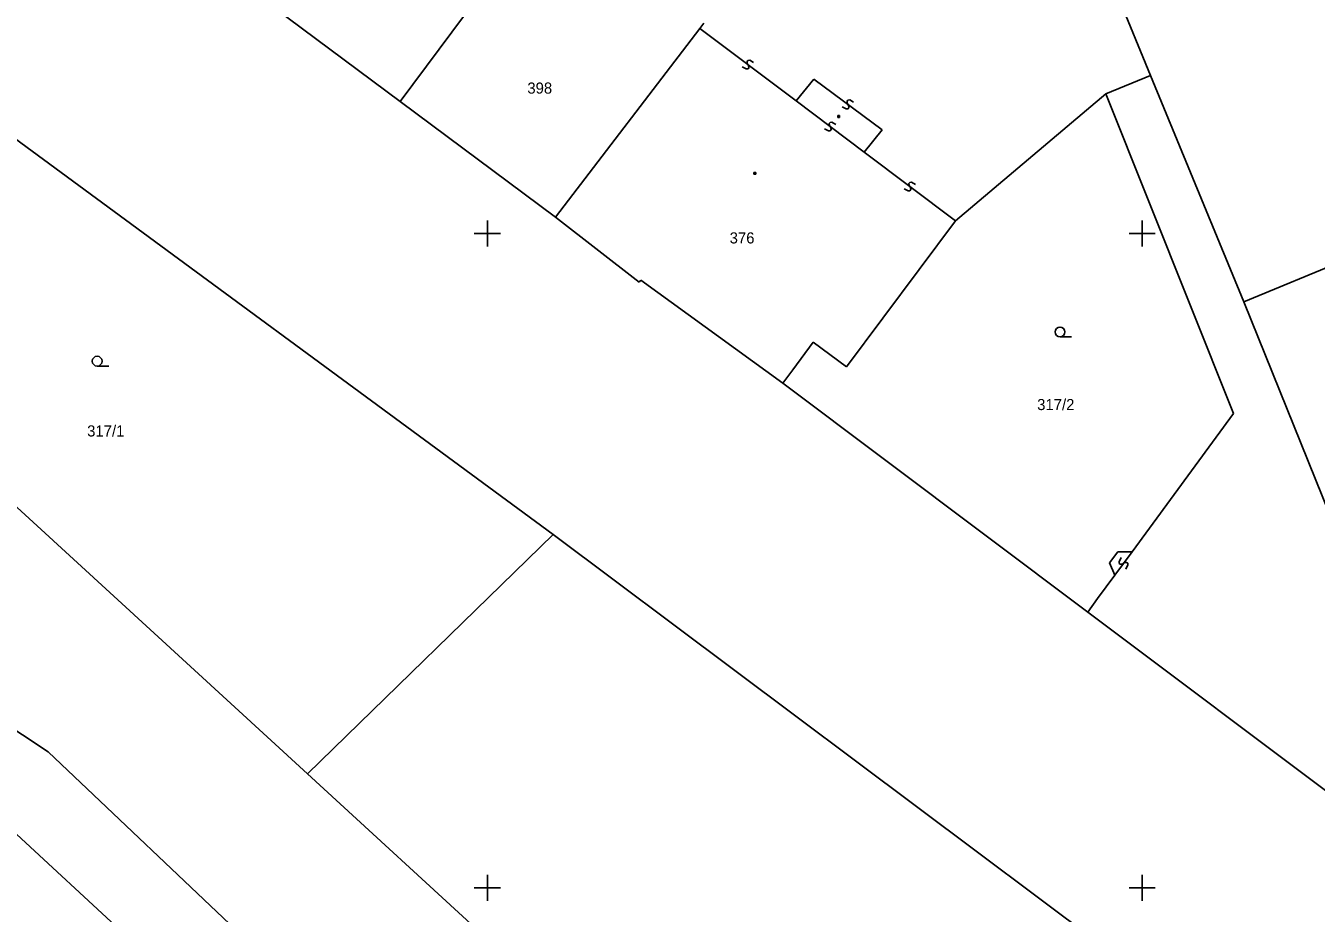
# Model space of a CAD drawing. Extents: x -492379 to -491966, y -1126153 to -1125860.
# Drawn here: x -492201.2 to -492142, y -1125961.2 to -1125920.5 of the extents above; entities that cross this region are included whole.
import ezdxf

# ---------------------------------------------------------------- set-up
doc = ezdxf.new("R2010")
doc.units = 0
doc.layers.add('katastrální mapa', color=7, linetype='Continuous')
doc.layers.add('síť', color=7, linetype='Continuous')

msp = doc.modelspace()

# ---------------------------------------------------------------- linework, layer by layer
at = {"layer": 'katastrální mapa'}
for p, q in [((-492183.99, -1125923.95), (-492177.35, -1125915)), ((-492152.78, -1125915.08), (-492149.61, -1125922.76)), ((-492191.15, -1125918.62), (-492183.99, -1125923.95)), ((-492208.16, -1125920.85), (-492176.98, -1125943.81)), ((-492176.88, -1125929.26), (-492170.27, -1125920.6)), ((-492170.27, -1125920.6), (-492170.09, -1125920.36)), ((-492170.27, -1125920.6), (-492165.85, -1125923.92)), ((-492168.07, -1125922.07), (-492168.1, -1125922.12)), ((-492167.98, -1125922.06), (-492168.07, -1125922.07)), ((-492167.8, -1125922.16), (-492167.98, -1125922.06)), ((-492168.14, -1125922.46), (-492168.32, -1125922.36)), ((-492168.05, -1125922.45), (-492168.14, -1125922.46)), ((-492168.1, -1125922.12), (-492168.09, -1125922.2)), ((-492168.09, -1125922.2), (-492168.03, -1125922.32)), ((-492168.02, -1125922.4), (-492168.05, -1125922.45)), ((-492168.03, -1125922.32), (-492168.02, -1125922.4)), ((-492145.34, -1125933.14), (-492118.89, -1125922.15)), ((-492165.85, -1125923.92), (-492165.05, -1125922.92)), ((-492165.05, -1125922.92), (-492161.91, -1125925.25)), ((-492151.67, -1125923.6), (-492149.61, -1125922.76)), ((-492149.61, -1125922.76), (-492145.34, -1125933.14)), ((-492158.55, -1125929.42), (-492151.67, -1125923.6)), ((-492151.67, -1125923.6), (-492145.82, -1125938.25)), ((-492183.99, -1125923.95), (-492176.88, -1125929.26)), ((-492165.85, -1125923.92), (-492162.74, -1125926.28)), ((-492163.56, -1125924.29), (-492163.74, -1125924.19)), ((-492163.47, -1125924.28), (-492163.56, -1125924.29)), ((-492163.49, -1125923.89), (-492163.52, -1125923.94)), ((-492163.52, -1125923.94), (-492163.51, -1125924.03)), ((-492163.51, -1125924.03), (-492163.45, -1125924.14)), ((-492163.4, -1125923.88), (-492163.49, -1125923.89)), ((-492163.44, -1125924.23), (-492163.47, -1125924.28)), ((-492163.45, -1125924.14), (-492163.44, -1125924.23)), ((-492163.22, -1125923.98), (-492163.4, -1125923.88)), ((-492164.3, -1125924.91), (-492164.34, -1125924.96)), ((-492164.34, -1125924.96), (-492164.32, -1125925.04)), ((-492164.32, -1125925.04), (-492164.27, -1125925.16)), ((-492164.22, -1125924.9), (-492164.3, -1125924.91)), ((-492164.03, -1125925), (-492164.22, -1125924.9)), ((-492163.95, -1125924.59), (-492163.86, -1125924.59)), ((-492163.95, -1125924.68), (-492163.95, -1125924.59)), ((-492163.86, -1125924.68), (-492163.95, -1125924.68)), ((-492163.86, -1125924.59), (-492163.86, -1125924.68)), ((-492164.37, -1125925.3), (-492164.56, -1125925.2)), ((-492164.29, -1125925.29), (-492164.37, -1125925.3)), ((-492164.25, -1125925.24), (-492164.29, -1125925.29)), ((-492164.27, -1125925.16), (-492164.25, -1125925.24)), ((-492162.74, -1125926.28), (-492161.91, -1125925.25)), ((-492162.74, -1125926.28), (-492158.55, -1125929.42)), ((-492167.79, -1125927.2), (-492167.7, -1125927.2)), ((-492167.79, -1125927.29), (-492167.79, -1125927.2)), ((-492167.7, -1125927.29), (-492167.79, -1125927.29)), ((-492167.7, -1125927.2), (-492167.7, -1125927.29)), ((-492160.72, -1125928.05), (-492160.91, -1125927.95)), ((-492160.65, -1125927.66), (-492160.69, -1125927.71)), ((-492160.69, -1125927.71), (-492160.68, -1125927.79)), ((-492160.68, -1125927.79), (-492160.61, -1125927.91)), ((-492160.57, -1125927.65), (-492160.65, -1125927.66)), ((-492160.6, -1125927.99), (-492160.64, -1125928.04)), ((-492160.61, -1125927.91), (-492160.6, -1125927.99)), ((-492160.38, -1125927.75), (-492160.57, -1125927.65)), ((-492160.64, -1125928.04), (-492160.72, -1125928.05)), ((-492176.88, -1125929.26), (-492173.05, -1125932.23)), ((-492163.54, -1125936.12), (-492158.55, -1125929.42)), ((-492173.05, -1125932.23), (-492172.97, -1125932.14)), ((-492172.97, -1125932.14), (-492166.47, -1125936.87)), ((-492145.34, -1125933.14), (-492141.08, -1125943.7)), ((-492166.01, -1125936.25), (-492165.07, -1125934.98)), ((-492165.07, -1125934.98), (-492163.54, -1125936.12)), ((-492153.76, -1125934.74), (-492153.23, -1125934.74)), ((-492197.88, -1125936.08), (-492197.35, -1125936.08)), ((-492166.47, -1125936.87), (-492166.01, -1125936.25)), ((-492166.47, -1125936.87), (-492152.49, -1125947.37)), ((-492150.46, -1125944.59), (-492145.82, -1125938.25)), ((-492203.01, -1125941.22), (-492188.24, -1125954.78)), ((-492215.33, -1125943.73), (-492200.12, -1125953.76)), ((-492188.24, -1125954.78), (-492176.98, -1125943.81)), ((-492176.98, -1125943.81), (-492142.23, -1125969.82)), ((-492151.5, -1125945.1), (-492151.12, -1125944.6)), ((-492151.5, -1125945.1), (-492151.25, -1125945.66)), ((-492151.25, -1125945.66), (-492150.46, -1125944.59)), ((-492151.12, -1125944.6), (-492150.46, -1125944.59)), ((-492150.96, -1125944.86), (-492151.06, -1125945.05)), ((-492151.06, -1125945.05), (-492151.05, -1125945.13)), ((-492151.05, -1125945.13), (-492151, -1125945.17)), ((-492151, -1125945.17), (-492150.91, -1125945.16)), ((-492150.91, -1125945.16), (-492150.8, -1125945.09)), ((-492150.8, -1125945.09), (-492150.71, -1125945.08)), ((-492150.71, -1125945.08), (-492150.66, -1125945.12)), ((-492150.66, -1125945.12), (-492150.65, -1125945.2)), ((-492152.04, -1125946.74), (-492151.25, -1125945.66)), ((-492150.65, -1125945.2), (-492150.75, -1125945.39)), ((-492152.49, -1125947.37), (-492152.04, -1125946.74)), ((-492152.49, -1125947.37), (-492127.23, -1125966.34)), ((-492200.12, -1125953.76), (-492184.32, -1125968.76)), ((-492188.24, -1125954.78), (-492170.54, -1125971.02)), ((-492202.19, -1125956.98), (-492186.86, -1125971.15))]:
    msp.add_line(p, q, dxfattribs=at)
for centre in [(-492153.76, -1125934.515), (-492197.88, -1125935.855)]:
    msp.add_circle(centre, 0.225, dxfattribs=at)
at = {"layer": 'síť'}
for p, q in [((-492180, -1125929.4), (-492180, -1125930.6)), ((-492150, -1125929.4), (-492150, -1125930.6)), ((-492180.6, -1125930), (-492179.4, -1125930)), ((-492150.6, -1125930), (-492149.4, -1125930)), ((-492180, -1125959.4), (-492180, -1125960.6)), ((-492150, -1125959.4), (-492150, -1125960.6)), ((-492180.6, -1125960), (-492179.4, -1125960)), ((-492150.6, -1125960), (-492149.4, -1125960))]:
    msp.add_line(p, q, dxfattribs=at)

# ---------------------------------------------------------------- texts
at = {"layer": 'katastrální mapa'}
for s, p in [('398', (-492178.17, -1125923.59)), ('376', (-492168.9, -1125930.46)), ('317/2', (-492154.81, -1125938.1)), ('317/1', (-492198.34, -1125939.31))]:
    msp.add_text(s, height=0.51, dxfattribs=at).set_placement(p)

doc.saveas('drawing.dxf')
